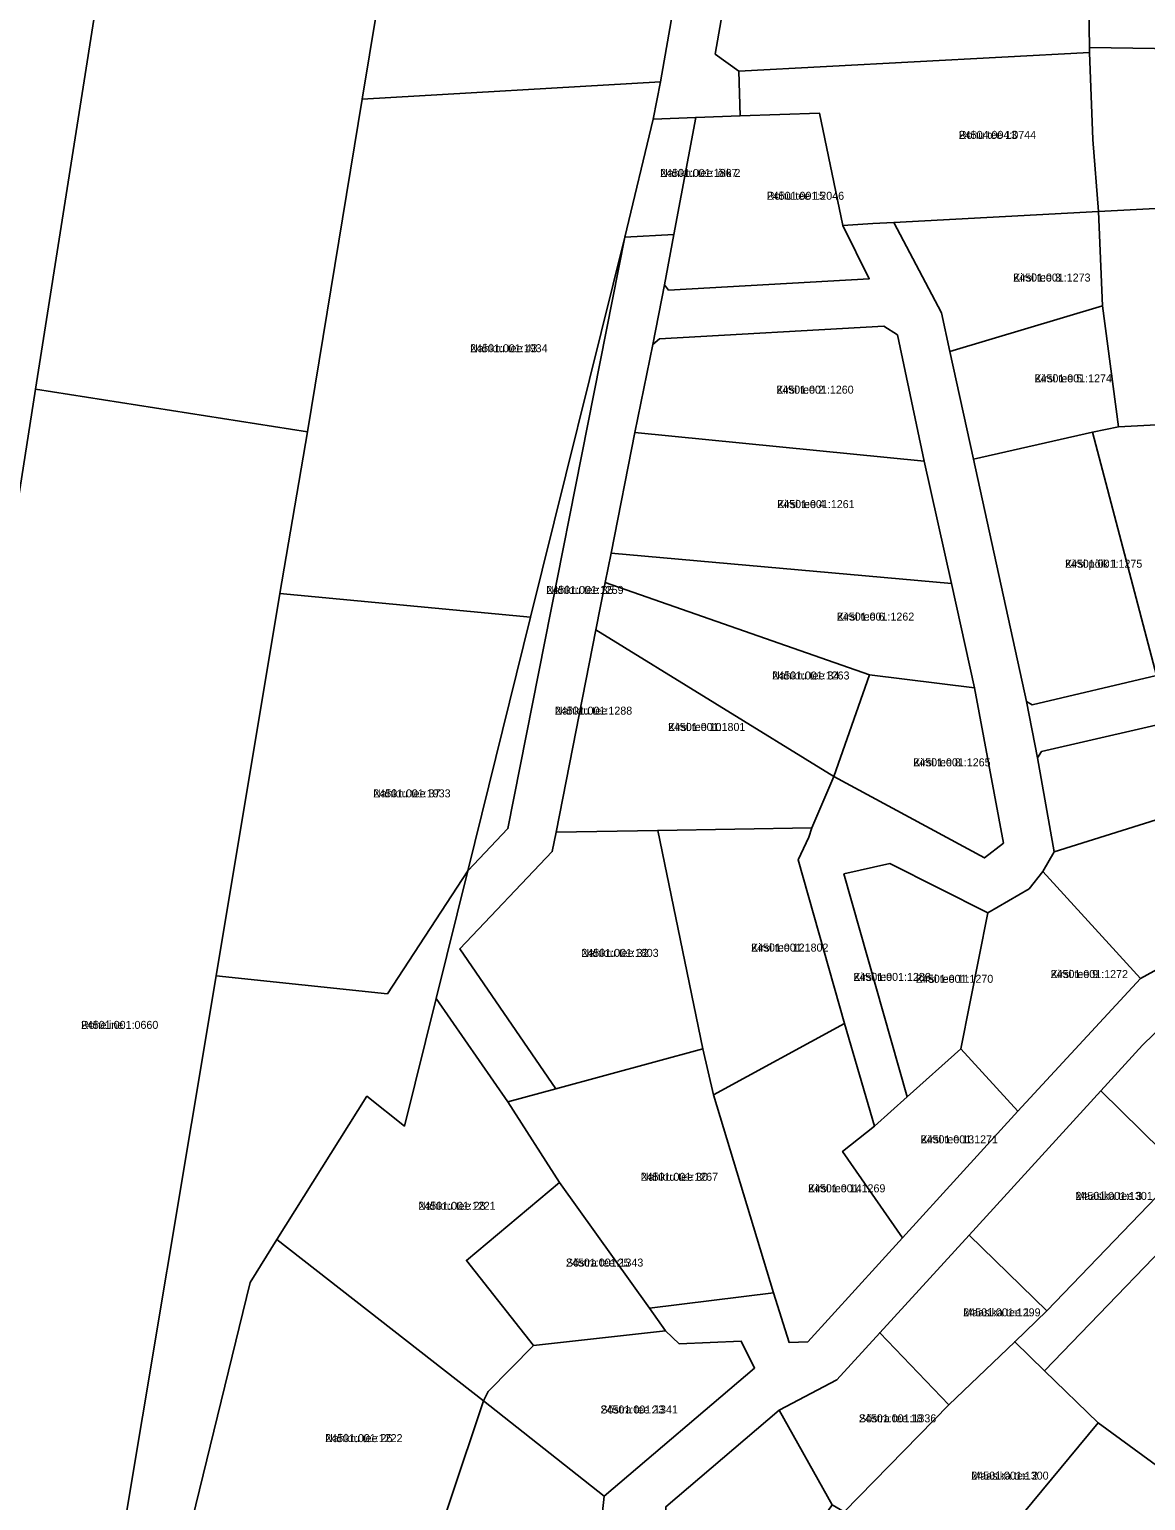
# Model space of a CAD drawing. Extents: x 551291 to 575799, y 6581704 to 6610137.
# Drawn here: x 558893.3 to 559102.6, y 6593937.5 to 6594213.3 of the extents above; entities that cross this region are included whole.
import ezdxf

# ---------------------------------------------------------------- set-up
doc = ezdxf.new("R2010")
doc.units = 0
for name, color, linetype in [('L_AADRESS', 7, 'Continuous'), ('PIIR', 7, 'Continuous'), ('TUNNUS', 7, 'Continuous')]:
    doc.layers.add(name, color=color, linetype=linetype)

msp = doc.modelspace()

# ---------------------------------------------------------------- linework, layer by layer
at = {"layer": 'PIIR'}
for points in [[(558980.66, 6594351.04), (558955.71, 6594200.23), (558945.47, 6594137.86), (558894.45, 6594145.91), (558927.31, 6594354.25), (558927.88, 6594357.82), (558981.83, 6594356.92)], [(558858.74, 6594327.54), (558860.94, 6594339.34), (558927.31, 6594354.25), (558894.45, 6594145.91), (558870.47, 6593993.01), (558817.21, 6594006.72), (558821.95, 6594035.9), (558831.57, 6594118.41), (558835.91, 6594150.5), (558837.22, 6594160.34), (558852.09, 6594274.66), (558855.82, 6594298.99)], [(558955.71, 6594200.23), (558980.66, 6594351.04), (559036.76, 6594347.25), (559011.63, 6594203.52)], [(559010.27, 6594196.52), (559011.63, 6594203.52), (559036.76, 6594347.25), (559045.95, 6594346.45), (559038.25, 6594302.34), (559034.87, 6594283.04), (559031.5, 6594263.8), (559026.9, 6594237.5), (559024.13, 6594221.62), (559021.87, 6594208.69), (559026.33, 6594205.49), (559026.59, 6594197.14), (559018.26, 6594196.82)], [(559091.89, 6594269.57), (559107.32, 6594269.22), (559107.35, 6594262.67), (559119.31, 6594262.74), (559119.35, 6594241.61), (559119.43, 6594238.08), (559112.4, 6594234.58), (559109.26, 6594228.91), (559109.56, 6594222.81), (559108.17, 6594222.79), (559108.36, 6594209.68), (559092.07, 6594209.91), (559091.93, 6594221.53), (559091.75, 6594237.49), (559091.55, 6594263.8)], [(559024.13, 6594221.62), (559091.93, 6594221.53), (559092.07, 6594209.91), (559092.1, 6594209.03), (559026.33, 6594205.49), (559021.87, 6594208.69)], [(559026.33, 6594205.49), (559092.1, 6594209.03), (559092.71, 6594192.66), (559093.81, 6594179.19), (559055.38, 6594177.11), (559051.44, 6594176.97), (559045.84, 6594176.59), (559041.49, 6594197.6), (559026.59, 6594197.14)], [(559092.07, 6594209.91), (559108.36, 6594209.68), (559108.39, 6594207.58), (559120.38, 6594207.76), (559121.09, 6594180.66), (559093.81, 6594179.19), (559092.71, 6594192.66), (559092.1, 6594209.03)], [(558945.47, 6594137.86), (558955.71, 6594200.23), (559011.63, 6594203.52), (559010.27, 6594196.52), (559004.93, 6594174.37), (558987.26, 6594103.14), (558940.29, 6594107.58)], [(559004.93, 6594174.37), (559010.27, 6594196.52), (559018.26, 6594196.82), (559014.13, 6594174.91)], [(559014.13, 6594174.91), (559018.26, 6594196.82), (559026.59, 6594197.14), (559041.49, 6594197.6), (559045.84, 6594176.59), (559050.8, 6594166.57), (559013.18, 6594164.46), (559012.37, 6594165.45)], [(559094.52, 6594161.53), (559093.81, 6594179.19), (559121.09, 6594180.66), (559132.51, 6594181.19), (559130.94, 6594156.84), (559127.94, 6594156.64), (559116.52, 6594139.85), (559097.53, 6594138.82)], [(559064.36, 6594160.17), (559055.38, 6594177.11), (559093.81, 6594179.19), (559094.52, 6594161.53), (559065.91, 6594152.92)], [(558975.52, 6594055.61), (558983.04, 6594063.52), (559004.93, 6594174.37), (559014.13, 6594174.91), (559012.37, 6594165.45), (559010.19, 6594154.26), (559006.82, 6594137.75), (559002.38, 6594115.13), (559001.28, 6594109.64), (558999.54, 6594100.79), (558992.07, 6594062.83), (558991.36, 6594059.21), (558974, 6594040.95), (558992.01, 6594014.7), (558983.02, 6594012.26), (558969.55, 6594031.66)], [(559011.46, 6594155.32), (559010.19, 6594154.26), (559012.37, 6594165.45), (559013.18, 6594164.46), (559050.8, 6594166.57), (559045.84, 6594176.59), (559051.44, 6594176.97), (559055.38, 6594177.11), (559064.36, 6594160.17), (559065.91, 6594152.92), (559070.32, 6594132.79), (559080.27, 6594087.34), (559082.35, 6594076.77), (559085.48, 6594059.17), (559083.32, 6594055.44), (559080.78, 6594052.21), (559073.06, 6594047.71), (559054.66, 6594056.95), (559046.04, 6594055.02), (559057.91, 6594013.25), (559051.79, 6594007.74), (559046.14, 6594026.97), (559037.46, 6594057.63), (559039.49, 6594061.93), (559040.06, 6594063.63), (559044.13, 6594073.29), (559072.41, 6594058.01), (559075.99, 6594060.79), (559070.55, 6594089.87), (559066.19, 6594109.43), (559061.12, 6594132.4), (559056.07, 6594156.07), (559053.51, 6594157.69)], [(558983.04, 6594063.52), (558975.52, 6594055.61), (558987.26, 6594103.14), (559004.93, 6594174.37)], [(559070.32, 6594132.79), (559065.91, 6594152.92), (559094.52, 6594161.53), (559097.53, 6594138.82), (559092.66, 6594137.82)], [(559083.08, 6594077.93), (559082.35, 6594076.77), (559080.27, 6594087.34), (559081.32, 6594086.72), (559104.68, 6594092.19), (559126.41, 6594097.28), (559127.56, 6594099.61), (559116.52, 6594139.85), (559127.94, 6594156.64), (559130.94, 6594156.84), (559164.79, 6594158.57), (559166.12, 6594151.18), (559163.54, 6594150.97), (559145.65, 6594150.08), (559127.76, 6594132.76), (559131.94, 6594117.82), (559139.27, 6594091.06), (559130.58, 6594088.89)], [(559061.12, 6594132.4), (559006.82, 6594137.75), (559010.19, 6594154.26), (559011.46, 6594155.32), (559053.51, 6594157.69), (559056.07, 6594156.07)], [(558860.47, 6593928.98), (558870.47, 6593993.01), (558894.45, 6594145.91), (558945.47, 6594137.86), (558940.29, 6594107.58), (558928.3, 6594035.88), (558909.88, 6593925.54), (558903.67, 6593906.99)], [(559104.68, 6594092.19), (559092.66, 6594137.82), (559097.53, 6594138.82), (559116.52, 6594139.85), (559127.56, 6594099.61), (559126.41, 6594097.28)], [(559066.19, 6594109.43), (559002.38, 6594115.13), (559006.82, 6594137.75), (559061.12, 6594132.4)], [(559080.27, 6594087.34), (559070.32, 6594132.79), (559092.66, 6594137.82), (559104.68, 6594092.19), (559081.32, 6594086.72)], [(559050.83, 6594092.34), (559001.28, 6594109.64), (559002.38, 6594115.13), (559066.19, 6594109.43), (559070.55, 6594089.87)], [(559044.13, 6594073.29), (558999.54, 6594100.79), (559001.28, 6594109.64), (559050.83, 6594092.34)], [(558928.3, 6594035.88), (558940.29, 6594107.58), (558987.26, 6594103.14), (558975.52, 6594055.61), (558960.44, 6594032.51)], [(558992.07, 6594062.83), (558999.54, 6594100.79), (559044.13, 6594073.29), (559040.06, 6594063.63), (559011.13, 6594063.16)], [(559072.41, 6594058.01), (559044.13, 6594073.29), (559050.83, 6594092.34), (559070.55, 6594089.87), (559075.99, 6594060.79)], [(559082.35, 6594076.77), (559083.08, 6594077.93), (559130.58, 6594088.89), (559134.29, 6594074.43), (559085.48, 6594059.17)], [(559083.32, 6594055.44), (559085.48, 6594059.17), (559134.29, 6594074.43), (559137.01, 6594064.38), (559111.64, 6594040.93), (559101.69, 6594035.42)], [(558991.36, 6594059.21), (558992.07, 6594062.83), (559011.13, 6594063.16), (559019.59, 6594022.22), (558992.01, 6594014.7), (558974, 6594040.95)], [(559019.59, 6594022.22), (559011.13, 6594063.16), (559040.06, 6594063.63), (559039.49, 6594061.93), (559037.46, 6594057.63), (559046.14, 6594026.97), (559021.6, 6594013.62)], [(559057.91, 6594013.25), (559046.04, 6594055.02), (559054.66, 6594056.95), (559073.06, 6594047.71), (559067.94, 6594022.19)], [(559067.94, 6594022.19), (559073.06, 6594047.71), (559080.78, 6594052.21), (559083.32, 6594055.44), (559101.69, 6594035.42), (559078.66, 6594010.52)], [(558978.48, 6593956.26), (558939.73, 6593986.47), (558956.59, 6594013.33), (558963.62, 6594007.74), (558969.55, 6594031.66), (558983.02, 6594012.26), (558992.73, 6593997.18), (558975.24, 6593982.55), (558987.86, 6593966.61), (558979.31, 6593958)], [(559109.44, 6593999.39), (559094.22, 6594014.32), (559102.03, 6594022.89), (559108.29, 6594028.94), (559115.42, 6594026.72), (559126.66, 6594018.97), (559126.89, 6594017.48)], [(559032.86, 6593976.47), (559021.6, 6594013.62), (559046.14, 6594026.97), (559051.79, 6594007.74), (559045.78, 6594003), (559057.04, 6593986.81), (559039.26, 6593967.31), (559035.76, 6593967.17)], [(558992.73, 6593997.18), (558983.02, 6594012.26), (558992.01, 6594014.7), (559019.59, 6594022.22), (559021.6, 6594013.62), (559032.86, 6593976.47), (559009.61, 6593973.58)], [(559057.04, 6593986.81), (559045.78, 6594003), (559051.79, 6594007.74), (559057.91, 6594013.25), (559067.94, 6594022.19), (559078.66, 6594010.52)], [(559083.68, 6593961.87), (559078.07, 6593967.3), (559084.08, 6593973.08), (559109.44, 6593999.39), (559126.89, 6594017.48), (559133.35, 6594013.41), (559115.99, 6593995.38)], [(559084.08, 6593973.08), (559069.51, 6593987.27), (559094.22, 6594014.32), (559109.44, 6593999.39)], [(558987.86, 6593966.61), (558975.24, 6593982.55), (558992.73, 6593997.18), (559009.61, 6593973.58), (559012.59, 6593969.35)], [(559093.75, 6593952.11), (559083.68, 6593961.87), (559115.99, 6593995.38), (559129.39, 6593984.52), (559114.93, 6593967.42), (559127.58, 6593956.67), (559110.45, 6593939.88)], [(559065.7, 6593955.46), (559052.76, 6593968.98), (559069.51, 6593987.27), (559084.08, 6593973.08), (559078.07, 6593967.3)], [(558942.85, 6593907.12), (558919.07, 6593914.47), (558934.7, 6593978.41), (558939.73, 6593986.47), (558978.48, 6593956.26), (558966.22, 6593919.61), (558952.05, 6593923.32)], [(559001.11, 6593938.37), (558978.48, 6593956.26), (558979.31, 6593958), (558987.86, 6593966.61), (559012.59, 6593969.35), (559015.16, 6593966.91), (559026.78, 6593967.4), (559029.3, 6593962.38)], [(559043.84, 6593936.76), (559033.92, 6593954.49), (559044.72, 6593960.18), (559052.76, 6593968.98), (559065.7, 6593955.46), (559046.11, 6593935.41)], [(559067.14, 6593920.06), (559046.11, 6593935.41), (559065.7, 6593955.46), (559078.07, 6593967.3), (559083.68, 6593961.87), (559093.75, 6593952.11)], [(558971.11, 6593916.96), (558966.22, 6593919.61), (558978.48, 6593956.26), (559001.11, 6593938.37), (559000.02, 6593928.41), (558975.92, 6593914.98)], [(559012.85, 6593930.16), (559012.67, 6593936.38), (559033.92, 6593954.49), (559043.84, 6593936.76), (559029.34, 6593915.49)], [(559084.64, 6593907.29), (559067.14, 6593920.06), (559093.75, 6593952.11), (559110.45, 6593939.88), (559103.32, 6593932.48), (559106.24, 6593930.2)]]:
    msp.add_lwpolyline(points, close=True, dxfattribs=at)
for points in [[(558909.88, 6593925.54), (558928.3, 6594035.88), (558960.44, 6594032.51), (558975.52, 6594055.61), (558969.55, 6594031.66), (558963.62, 6594007.74), (558956.59, 6594013.33), (558939.73, 6593986.47), (558934.7, 6593978.41), (558919.07, 6593914.47)], [(559000.02, 6593928.41), (559001.11, 6593938.37), (559029.3, 6593962.38), (559026.78, 6593967.4), (559015.16, 6593966.91), (559012.59, 6593969.35), (559009.61, 6593973.58), (559032.86, 6593976.47), (559035.76, 6593967.17), (559039.26, 6593967.31), (559057.04, 6593986.81), (559078.66, 6594010.52), (559101.69, 6594035.42), (559111.64, 6594040.93)], [(559254.15, 6593930.55), (559217.11, 6593956.06), (559215.23, 6593955.78), (559207.3, 6593960.67), (559185.12, 6593975.18), (559168.66, 6593986.87), (559162.37, 6593991.17), (559162.14, 6593995.49), (559148.52, 6594005.87), (559137.72, 6594013.92), (559133.35, 6594013.41), (559126.89, 6594017.48), (559126.66, 6594018.97), (559115.42, 6594026.72), (559108.29, 6594028.94), (559102.03, 6594022.89), (559094.22, 6594014.32), (559069.51, 6593987.27), (559052.76, 6593968.98), (559044.72, 6593960.18), (559033.92, 6593954.49), (559012.67, 6593936.38)]]:
    msp.add_lwpolyline(points, dxfattribs=at)

# ---------------------------------------------------------------- texts
at = {"layer": 'L_AADRESS'}
for s, p in [('Rohu tee 13', (559067.59, 6594192.81)), ('Nahkru tee lõik 2', (559011.59, 6594185.67)), ('Rohu tee 15', (559031.58, 6594181.39)), ('Kirsi tee 3', (559077.79, 6594166.06)), ('Nahkru tee 43', (558975.96, 6594152.81)), ('Kirsi tee 5', (559081.8, 6594147.16)), ('Kirsi tee 2', (559033.37, 6594145.04)), ('Kirsi tee 4', (559033.55, 6594123.59)), ('Kirsi põik 1', (559087.5, 6594112.41)), ('Nahkru tee 35', (558990.23, 6594107.5)), ('Kirsi tee 6', (559044.73, 6594102.5)), ('Nahkru tee 34', (559032.59, 6594091.46)), ('Nahkru tee', (558991.84, 6594084.87)), ('Kirsi tee 10', (559013.06, 6594081.81)), ('Kirsi tee 8', (559059.05, 6594075.18)), ('Nahkru tee 37', (558957.78, 6594069.36)), ('Nahkru tee 32', (558996.8, 6594039.46)), ('Kirsi tee 12', (559028.64, 6594040.45)), ('Kirsi tee 9', (559084.81, 6594035.49)), ('Kirsi tee', (559047.83, 6594034.95)), ('Kirsi tee 11', (559059.55, 6594034.6)), ('Roheline', (558902.97, 6594025.96)), ('Kirsi tee 13', (559060.43, 6594004.5)), ('Nahkru tee 30', (559007.94, 6593997.48)), ('Kirsi tee 14', (559039.32, 6593995.32)), ('Maasika tee 3', (559089.47, 6593993.9)), ('Nahkru tee 28', (558966.23, 6593992.04)), ('Sõstra tee 25', (558993.92, 6593981.4)), ('Maasika tee 1', (559068.42, 6593972.07)), ('Sõstra tee 23', (559000.41, 6593953.86)), ('Sõstra tee 18', (559048.86, 6593952.2)), ('Nahkru tee 26', (558948.77, 6593948.49)), ('Maasika tee 2', (559069.93, 6593941.46))]:
    msp.add_text(s, height=1.5, dxfattribs=at).set_placement(p)
at = {"layer": 'TUNNUS'}
for s, p in [('24504:004:0744', (559067.59, 6594192.81)), ('24501:001:1867', (559011.59, 6594185.67)), ('24501:001:2046', (559031.58, 6594181.39)), ('24501:001:1273', (559077.79, 6594166.06)), ('24501:001:1934', (558975.96, 6594152.81)), ('24501:001:1274', (559081.8, 6594147.16)), ('24501:001:1260', (559033.37, 6594145.04)), ('24501:001:1261', (559033.55, 6594123.59)), ('24501:001:1275', (559087.5, 6594112.41)), ('24501:001:1259', (558990.23, 6594107.5)), ('24501:001:1262', (559044.73, 6594102.5)), ('24501:001:1263', (559032.59, 6594091.46)), ('24501:001:1288', (558991.84, 6594084.87)), ('24501:001:1801', (559013.06, 6594081.81)), ('24501:001:1265', (559059.05, 6594075.18)), ('24501:001:1933', (558957.78, 6594069.36)), ('24501:001:1803', (558996.8, 6594039.46)), ('24501:001:1802', (559028.64, 6594040.45)), ('24501:001:1272', (559084.81, 6594035.49)), ('24501:001:1286', (559047.83, 6594034.95)), ('24501:001:1270', (559059.55, 6594034.6)), ('24501:001:0660', (558902.97, 6594025.96)), ('24501:001:1271', (559060.43, 6594004.5)), ('24501:001:1267', (559007.94, 6593997.48)), ('24501:001:1269', (559039.32, 6593995.32)), ('24501:001:1301', (559089.47, 6593993.9)), ('24501:001:1221', (558966.23, 6593992.04)), ('24501:001:1343', (558993.92, 6593981.4)), ('24501:001:1299', (559068.42, 6593972.07)), ('24501:001:1341', (559000.41, 6593953.86)), ('24501:001:1336', (559048.86, 6593952.2)), ('24501:001:1222', (558948.77, 6593948.49)), ('24501:001:1300', (559069.93, 6593941.46))]:
    msp.add_text(s, height=1.5, dxfattribs=at).set_placement(p)

doc.saveas('drawing.dxf')
